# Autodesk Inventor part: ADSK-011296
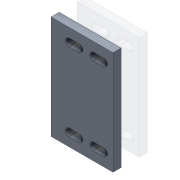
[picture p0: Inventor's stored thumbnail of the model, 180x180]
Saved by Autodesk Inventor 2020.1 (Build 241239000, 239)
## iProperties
Created: 1999-11
Part Number: ADSK-011296
Material: Pearson Aluminium
Document SubType Name: Modeling
Designer: sspink
Density: 2.71 g/cm^3
Appearance: Pearson-Aluminum
Mass: 242.478 g
Surface Area: 240.86 cm^2
Volume: 89.4753 cm^3
Control State: 0
Checked Out: False
Last Check In By: sspink
Last Check In Date: 1999-12-22
Master: False
Shininess: 35.0
Length Units: 11269
Angle Units: 11279
Time Units: 11290
Mass Units: 11283
Length Display Precision: 3
Angle Display Precision: 2
Compacted: True
Cutlength: 5
Material Desc: FLAT,ALUM,0.375 X 3.00
Material_number: A087231
Dimensions: 76x127x10 mm
Mass: 0,242 kg
DocNumber: ADSK-011296.ipt
Folder: 01 - Themengebiete\Simplification\01 - Packaging machine\
VDS_Category: 3D Komponenten
Density: 2.71
Volumn: 85.67092044031848
Area: 238.72492261804229
PropertySet Name: Model Information
Author: sspink
Revision Number: -
Title: base plate
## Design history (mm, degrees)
workpoint "Arbeitspunkt1"
workpoint "Arbeitspunkt2"
workpoint "Arbeitspunkt3"
workpoint "Arbeitspunkt4"
workaxis "Arbeitsachse1"
workaxis "Arbeitsachse2"
workaxis "Arbeitsachse3"
workaxis "Arbeitsachse4"
workplane "Arbeitsebene3"
node "Rectangular Pattern1" dims "d9" = 20, "d11" = 95.5, "d12" = 20, "d14" = 32
node "Solide1"
  node "Extrusion1" dims "d1" = 10, "d2" = 0
  node "Extrusion2" dims "d7" = 9.525, "d8" = 0
sketch "Sketch1"
  geometry: L1 (-12.5, 0)-(-12.5, 127); L2 (0, 0)-(0, 127); L3 (0, 127)-(-12.5, 127); L4 (-12.5, 0)-(0, 0); L5 (0, 127)-(63.5, 127); L6 (63.5, 127)-(63.5, 0) reference; L7 (63.5, 0)-(0, 0) reference
  constraints: 14 end point, 4 perpendicular, 2 parallel, 1 horizontal, 1 vertical
  dimensions: "d0" = 63.5 distance of L6.end L2.start; "d15" = 127 distance of L5.end L6.end; "d16" = 12.5 distance of L2.end L1.end
sketch "Sketch2"
  geometry: L1 (-12.5, 0)-(-12.5, 127) reference; L2 (22.25, 106.75)-(9.75, 106.75); L3 (9.75, 106.75)-(9.75, 115.75); L4 (9.75, 115.75)-(22.25, 115.75); L5 (22.25, 115.75)-(22.25, 106.75); L6 (22.25, 111.25)-(9.75, 111.25); L7 (-12.5, 63.5)-(63.5, 63.5); L8 (63.5, 127)-(63.5, 0) reference
  constraints: 12 end point, 4 midpoint, 3 horizontal, 2 parallel, 2 vertical alignment, 1 perpendicular, 4 other
  dimensions: "d3" = 9 distance of L4.end L2.start; "d4" = 12.5 distance of L2.start L2.end; "d5" = 22.25 distance from line of L6.end L1; "d20" = 47.75 distance between parallel lines of L7 L6
node "Corps solides"
node "Corps surfaciques"
